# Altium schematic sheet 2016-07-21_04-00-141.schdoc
size 679 x 287 mm; SheetNumber: 1; SheetTotal: 1
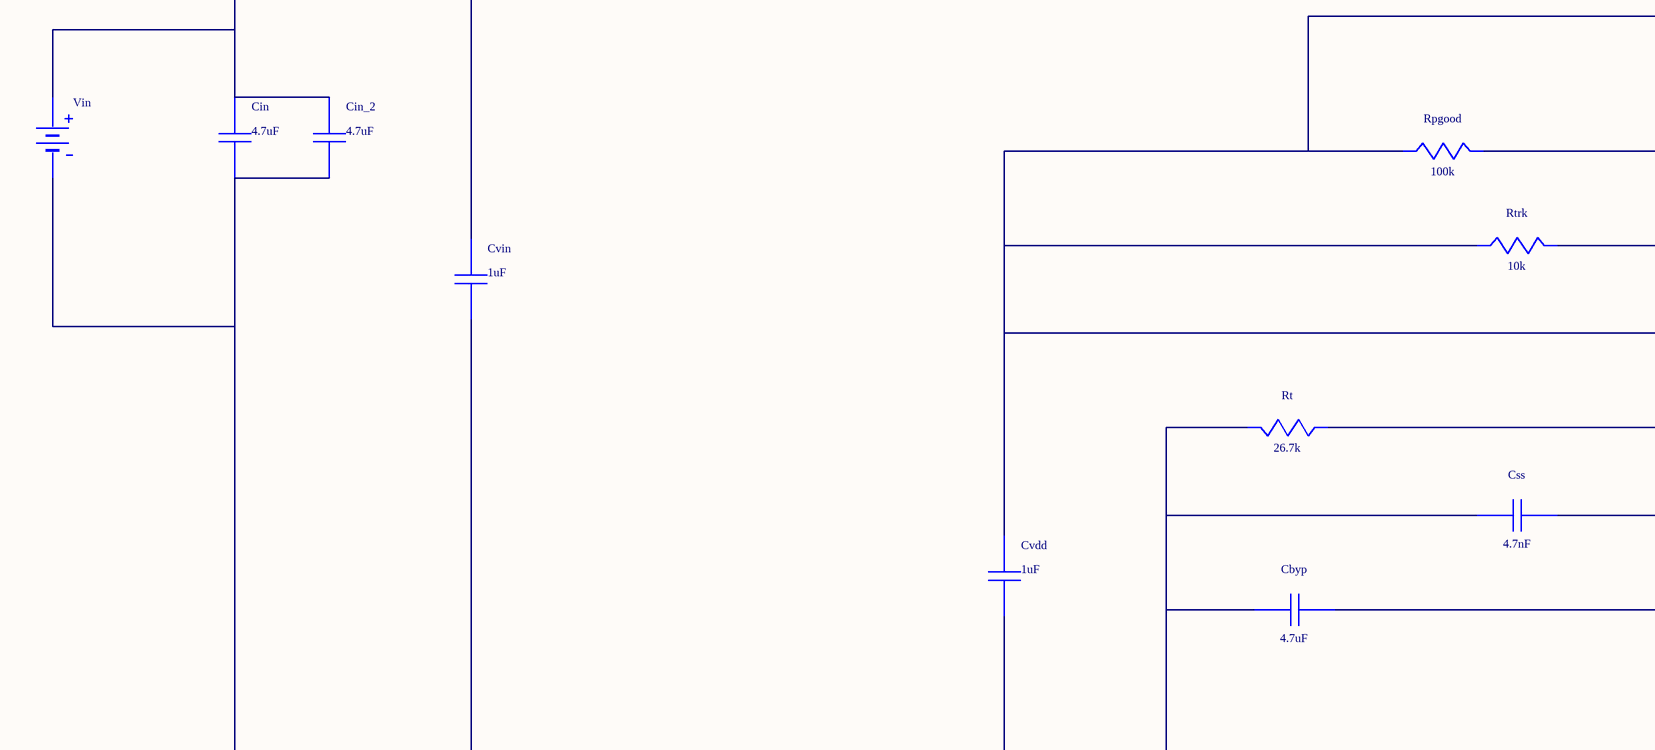
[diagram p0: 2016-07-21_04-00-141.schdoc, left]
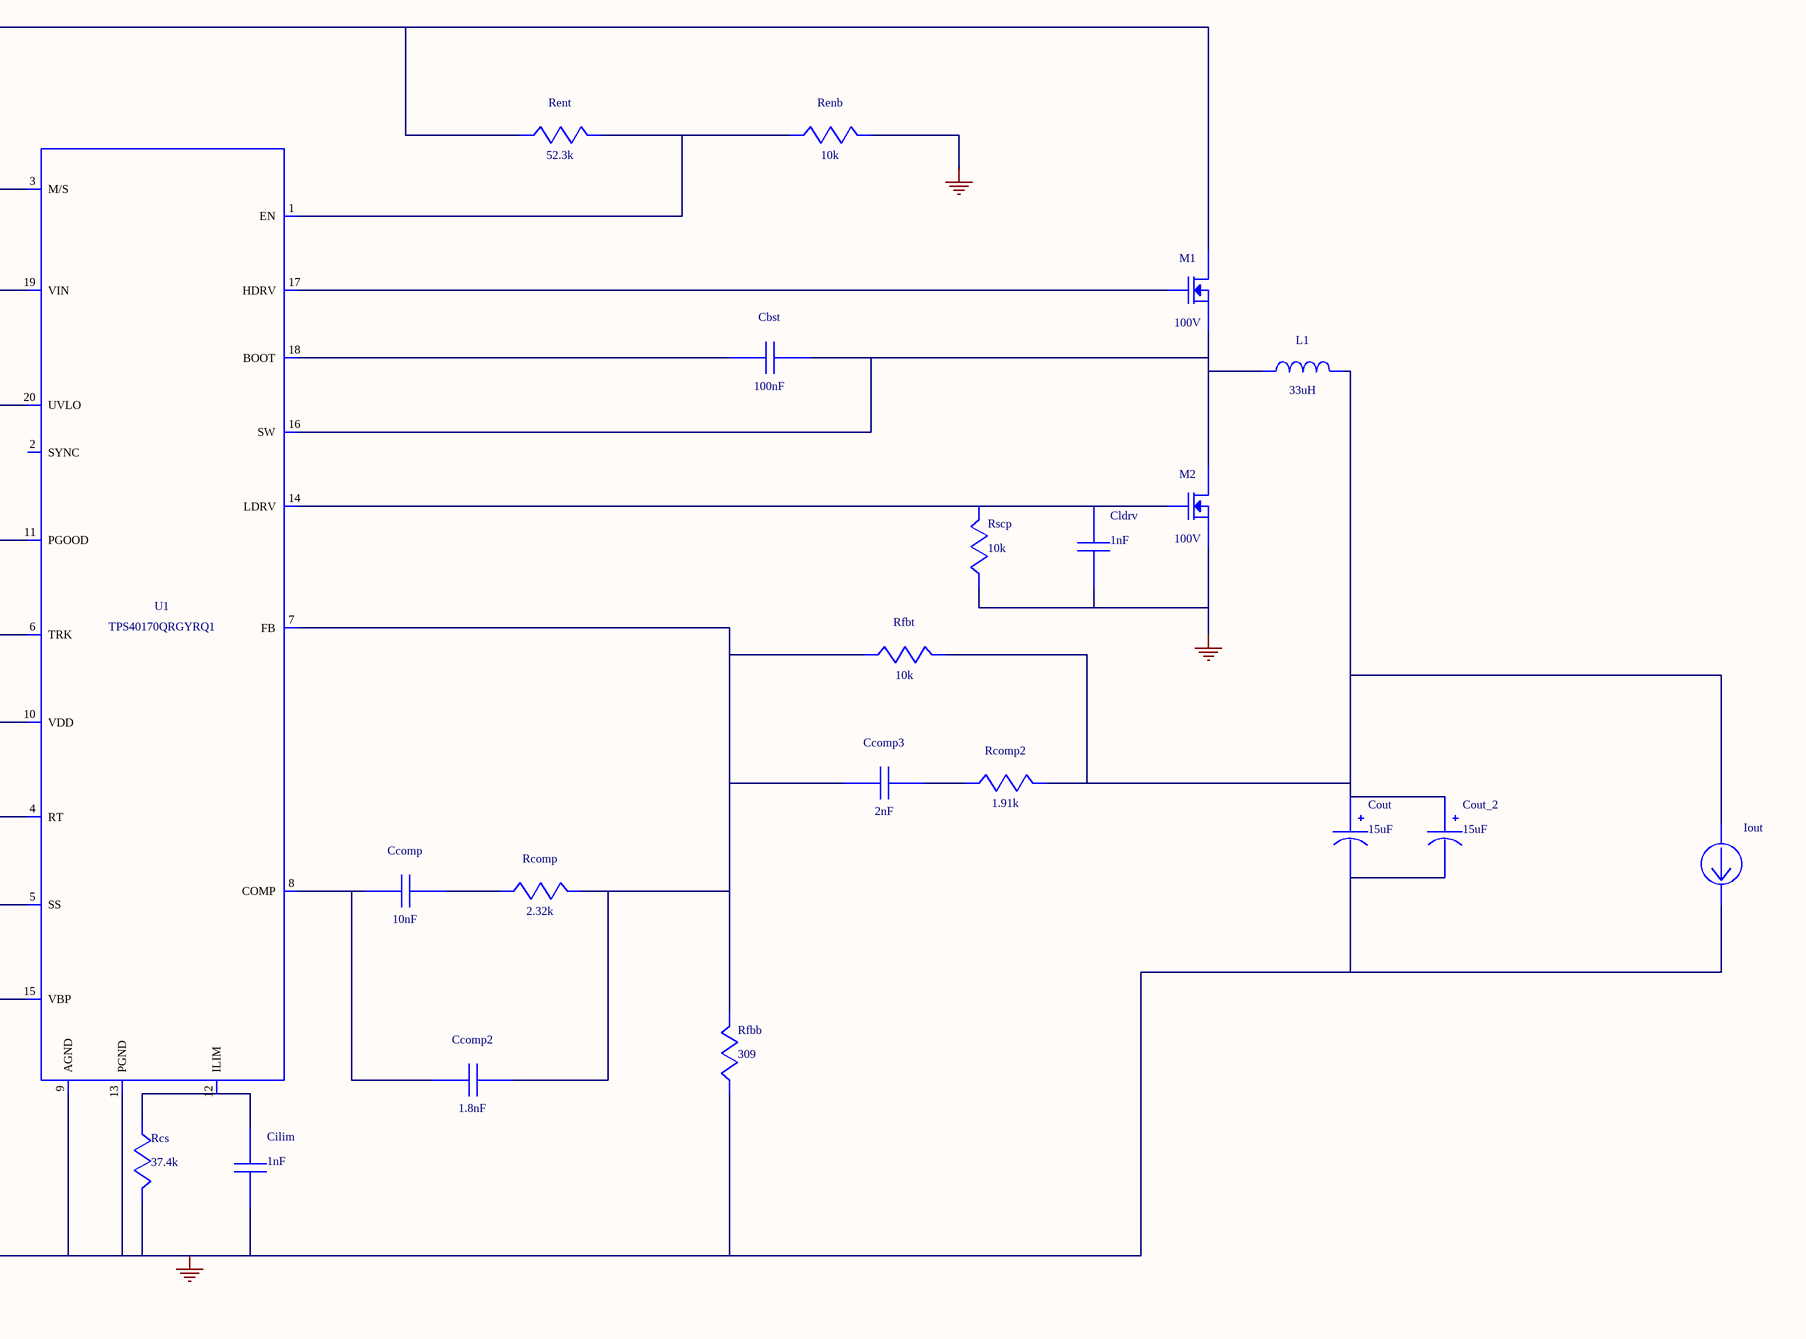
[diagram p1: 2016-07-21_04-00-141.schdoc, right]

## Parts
Cbst  value 100nF  (hidden comment: HMK212B7104KG-T)
Cbyp  value 4.7uF  (hidden comment: GRM21BR61E475KA12L)
Ccomp  value 10nF  (hidden comment: GRM216R71H103KA01D)
Ccomp2  value 1.8nF  (hidden comment: GRM033R71A182KA01D)
Ccomp3  value 2nF  (hidden comment: GRM1885C1H202JA01D)
Cilim  value 1nF  (hidden comment: GRM216R71E102KA01D)
Cin  value 4.7uF  (hidden comment: C3225X7S2A475M200AB)
Cin_2  value 4.7uF  (hidden comment: C3225X7S2A475M200AB)
Cldrv  value 1nF  (hidden comment: GRM216R71E102KA01D)
Cout  value 15uF  (hidden comment: UUD1E150MCL1GS)
Cout_2  value 15uF  (hidden comment: UUD1E150MCL1GS)
Css  value 4.7nF  (hidden comment: GRM033R70J472KA01D)
Cvdd  value 1uF  (hidden comment: GRM188R61C105KA93D)
Cvin  value 1uF  (hidden comment: C3216X5R2A105K)
Iout  WB_CURRENT_LOAD  (value not drawn)
L1  value 33uH  (hidden comment: IHLP6767GZER330M11)
M1  value 100V  (hidden comment: CSD19534Q5A)
M2  value 100V  (hidden comment: CSD16323Q3)
Rcomp  value 2.32k  (hidden comment: CRCW04022K32FKED)
Rcomp2  value 1.91k  (hidden comment: CRCW04021K91FKED)
Rcs  value 37.4k  (hidden comment: CRCW040237K4FKED)
Renb  value 10k  (hidden comment: CRCW040210K0FKED)
Rent  value 52.3k  (hidden comment: CRCW040252K3FKED)
Rfbb  value 309  (hidden comment: CRCW0402309RFKED)
Rfbt  value 10k  (hidden comment: CRCW040210K0FKED)
Rpgood  value 100k  (hidden comment: CRCW0402100KFKED)
Rscp  value 10k  (hidden comment: CRCW040210K0FKED)
Rt  value 26.7k  (hidden comment: CRCW040226K7FKED)
Rtrk  value 10k  (hidden comment: CRCW040210K0FKED)
U1  TPS40170QRGYRQ1
Vin  WB_BATTERY  (value not drawn)

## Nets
0: Cbyp.2 Cilim.1 Cin.2 Cin_2.2 Cldrv.2 Cout.2(-) Cout_2.2(-) Css.2 Cvdd.2 Cvin.2 Iout.2(-) M2.1(Source) M2.2(Source) M2.3(Source) Rcs.1 Renb.1 Rfbb.2 Rscp.2 Rt.1 U1.9(AGND) U1.13(PGND) U1.21(ETPAD) Vin.2(-)
NetCbst_1: Cbst.1 U1.18(BOOT)
NetCbst_2: Cbst.2 L1.1 M1.1(Source) M1.2(Source) M1.3(Source) M2.5(Drain) M2.6(Drain) M2.7(Drain) M2.8(Drain) M2.9(Drain) U1.16(SW)
NetCbyp_1: Cbyp.1 U1.15(VBP)
NetCcomp2_1: Ccomp2.1 Ccomp3.2 Rcomp.1 Rfbb.1 Rfbt.2 U1.7(FB)
NetCcomp3_1: Ccomp3.1 Rcomp2.2
NetCcomp_1: Ccomp.1 Rcomp.2
NetCcomp_2: Ccomp.2 Ccomp2.2 U1.8(COMP)
NetCilim_2: Cilim.2 Rcs.2 U1.12(ILIM)
NetCin_1: Cin.1 Cin_2.1 Cvin.1 M1.5(Drain) M1.6(Drain) M1.7(Drain) M1.8(Drain) M1.9(Drain) Rent.2 U1.3(M/S) U1.19(VIN) Vin.1(+)
NetCldrv_1: Cldrv.1 M2.4(Gate) Rscp.1 U1.14(LDRV)
NetCout_1: Cout.1(+) Cout_2.1(+) Iout.1(+) L1.2 Rcomp2.1 Rfbt.1
NetCss_1: Css.1 U1.5(SS)
NetCvdd_1: Cvdd.1 Rpgood.2 Rtrk.2 U1.10(VDD) U1.20(UVLO)
NetM1_4: M1.4(Gate) U1.17(HDRV)
NetRenb_2: Renb.2 Rent.1 U1.1(EN)
NetRpgood_1: Rpgood.1 U1.11(PGOOD)
NetRt_2: Rt.2 U1.4(RT)
NetRtrk_1: Rtrk.1 U1.6(TRK)

Not connected (* = marked no-connect by the designer): U1 2(SYNC)

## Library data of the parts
Cbst = HMK212B7104KG-T: Manufacturer Name: Taiyo Yuden
Cbyp = GRM21BR61E475KA12L: GRM21BR61E475KA1; Manufacturer Name: MuRata
Ccomp = GRM216R71H103KA01D: GRM216R71H103KA0; Manufacturer Name: MuRata
Ccomp2 = GRM033R71A182KA01D: GRM033R71A182KA0; Manufacturer Name: MuRata
Ccomp3 = GRM1885C1H202JA01D: GRM1885C1H202JA0; Manufacturer Name: MuRata
Cilim Cldrv = GRM216R71E102KA01D: GRM216R71E102KA0; Manufacturer Name: MuRata
Cin Cin_2 = C3225X7S2A475M200AB: C3225X7S2A475M20; Manufacturer Name: TDK
Cout Cout_2 = UUD1E150MCL1GS: Manufacturer Name: Nichicon
Css = GRM033R70J472KA01D: GRM033R70J472KA0; Manufacturer Name: MuRata
Cvdd = GRM188R61C105KA93D: GRM188R61C105KA9; Manufacturer Name: MuRata
Cvin = C3216X5R2A105K: Manufacturer Name: TDK
L1 = IHLP6767GZER330M11: IHLP6767GZER330M; Manufacturer Name: Vishay-Dale
M1 = CSD19534Q5A: Manufacturer Name: Texas Instruments
M2 = CSD16323Q3: CSD19537Q3; Manufacturer Name: Texas Instruments
Rcomp = CRCW04022K32FKED: Manufacturer Name: Vishay-Dale
Rcomp2 = CRCW04021K91FKED: Manufacturer Name: Vishay-Dale
Rcs = CRCW040237K4FKED: Manufacturer Name: Vishay-Dale
Renb Rfbt Rscp Rtrk = CRCW040210K0FKED: Manufacturer Name: Vishay-Dale
Rent = CRCW040252K3FKED: Manufacturer Name: Vishay-Dale
Rfbb = CRCW0402309RFKED: Manufacturer Name: Vishay-Dale
Rpgood = CRCW0402100KFKED: Manufacturer Name: Vishay-Dale
Rt = CRCW040226K7FKED: Manufacturer Name: Vishay-Dale
U1 = TPS40170QRGYRQ1: Manufacturer Name: Texas Instruments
